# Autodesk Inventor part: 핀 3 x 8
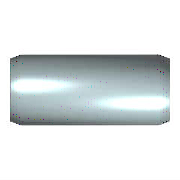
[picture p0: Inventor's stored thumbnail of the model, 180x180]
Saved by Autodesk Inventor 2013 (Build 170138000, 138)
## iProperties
IsCustomPart: 1
Created: 2012-02
Part Number: 핀 3 x 8
Material: 강철, 연강
Description: 평행 핀
Document SubType Name: Modeling
Standard: KS B 1320
Designer: mduedu
Standards Organization: KS
Language: ko-KR
Size Designation: B 3 x  8
Categories: <MemberInstance><Categories><Category DisplayName="조임쇠" InternalName="e4da775c-781d-43d5-af7c-5136215cf5a6" Mnemonic="FSTN"><Category DisplayName="핀" InternalNa
Density: 7.86 g/cm^3
Mass: 0.439658 g
Surface Area: 0.870195 cm^2
Volume: 0.0559361 cm^3
Author: mduedu
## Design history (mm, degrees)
sketch "스케치"
  geometry: C1 r 1.5 at (0, 0); 1 further point
  constraints: 1 centre point, 1 coincident
  dimensions: "d1" = 3 diameter of C1 (= NND)
extrude "본체" new body sketch "스케치" distance "d2" = 8 (= NLG); taper "d3" = 0 deg
chamfer "스케치2" distance "d8" = 0.5 (= PHH); stored, may be unused: angle "d9" = 15 deg (= FAWI), second distance "d12" = 0.5 (= PHH)
body "Solid1"
chamfer "모따기1" distance "d4" = 0.5 (= PHH); stored, may be unused: angle "d5" = 15 deg (= FAWI), second distance "d11" = 0.5 (= PHH)
other parameters: "NND" = 3 [user parameter; used in 1 equation term], "NLG" = 8 [user parameter; used in 1 equation term], "PHH" = 0.5 [user parameter; used in 4 equation terms], "FAWI" = 15 deg [user parameter; used in 2 equation terms], "d13" = 0, "d15" = 0, "d16" = 0, "KAH" = 0.4 [user parameter]
